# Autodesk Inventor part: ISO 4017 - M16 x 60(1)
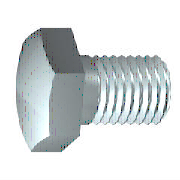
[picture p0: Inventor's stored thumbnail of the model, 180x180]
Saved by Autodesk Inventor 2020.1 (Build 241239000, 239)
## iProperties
Created: 2019-01
Part Number: ISO 4017 - M16 x 60(1)
Material: Stahl, weich
Description: Sechskantschraube
Document SubType Name: Modeling
Standard: DIN EN 24 017
Designer: lutzd
Standards Organization: DIN
Language: de-DE
Size Designation: M16 x 60
Categories: <MemberInstance><Categories><Category DisplayName="Verbindungselemente" InternalName="e4da775c-781d-43d5-af7c-5136215cf5a6" Mnemonic="FSTN"><Category DisplayNam
Mass: 132.821 g
Surface Area: 47.7353 cm^2
Volume: 16.9199 cm^3
Density: 7.85 g/cm^3
Appearance: Halbpoliert
IsCustomPart: 0
Author: lutzd
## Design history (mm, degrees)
workplane "Work Plane1"
sketch "Skizze1"
  geometry: L1 (0, 11.245)-(0, 8); L2 (6, 8)-(60, 8); L3 (60, 8)-(60, 0); L4 (60, 0)-(-0.8, 0); L5 (-12.96, 0)-(72.16, 0) reference; L6 (-0.8, 0)-(-0.8, 11.245); L7 (-0.8, 11.245)-(0, 11.245); L8 (6, 8)-(4.773, 8); L9 (4.773, 8)-(0, 8); L10 (0, -2.249)-(0, 13.494) reference
  constraints: 16 end point, 2 collinear, 2 perpendicular, 1 parallel
  dimensions: "d0" = 60 distance between parallel lines of L3 L1 (= NLG); "d1" = 54 distance from line of L2.start L3 (= GEL); "d2" = 16 diameter of L2 L4 (= GD); "d9" = 0.8001 distance between parallel lines of L6 L1 (computed from SD); "d10" = 22.49 diameter of L7 L4 (= SD2); "d13" = 1.227 distance of L2.start L8.end (computed from GAL); "d14" = 16 diameter of L9 L4 (= BDM)
revolve "Körper" sketch "Skizze1" stored, may be unused: angle "d12" = 90 deg
sketch "Skizze2"
  geometry: L1 (0, 13.856)-(12, 6.928); L2 (12, 6.928)-(12, -6.928); L3 (12, -6.928)-(0, -13.856); L4 (0, -13.856)-(-12, -6.928); L5 (-12, -6.928)-(-12, 6.928); L6 (-12, 6.928)-(0, 13.856); 2 further points
  constraints: 12 end point, 1 coincident, 1 vertical, 11 other
  dimensions: "d11" = 24 distance between parallel lines of L5 L2 (= SW)
extrude "Kopf" join sketch "Skizze2" distance "d3" = 9.2 (= KOH - SD); taper "d4" = 0 deg
sketch "Skizze4"
  geometry: L1 (-10, 12)-(-10, 13.856); L2 (-10, 13.856)-(-8.928, 13.856); L3 (-8.928, 13.856)-(-10, 12); L4 (-11.84, 0)-(1.04, 0) reference; L5 (-0.8, 13.856)-(-10, 13.856) reference; L6 (-10, 6.928)-(-10, 13.856) reference
  constraints: 6 end point, 2 collinear, 1 perpendicular, 1 vertical
  dimensions: "d5" = 30 deg angle of L3 L1 (= ANG1); "d19" = 24 diameter of L1.start L4 (= SW0)
revolve "Fase1" stored, may be unused: angle "d21" = 90 deg
body "Solid1"
feature "Gewinde" dims "d15" = 54 (= GEL), "d16" = 0
chamfer "Fase2" distance "d6" = 1.2269 (= -0.5 x SPD + 0.5 x GD); stored, may be unused: second distance "d7" = 1.227 (computed from GUL), angle "d55" = 45 deg
other parameters: "NLG" = 60 [user parameter; used in 1 equation term], "GD" = 16 (= NND) [user parameter; used in 2 equation terms], "BDM" = 16 (= NND) [user parameter; used in 1 equation term], "KOH" = 10 [user parameter; used in 1 equation term], "GEL" = 54 [user parameter; used in 2 equation terms], "SW" = 24 [user parameter; used in 2 equation terms], "SW0" = 24 (= SW) [user parameter; used in 1 equation term], "SPD" = 13.5462 (= NND - 1.2269 x PTC) [user parameter; used in 1 equation term], "SD2" = 22.49 [user parameter; used in 2 equation terms], "SD" = 0.8 [user parameter; used in 2 equation terms], "ANG1" = 30 deg [user parameter; used in 1 equation term], "GAL" = 1.2269 (= 0.61345 x PTC) [user parameter; used in 1 equation term], "GUL" = 1.2269 (= 0.61345 x PTC) [user parameter; used in 1 equation term], "d8" = 0, "RR" = 0.6 [user parameter], "d57" = 0, "d58" = 0, "TPU" = 5 (computed from PTC) [user parameter], "GD1" = 13.5462 (= THREADDIA - 1.2269 x PTC) [user parameter], "THREADDIA" = 16 [user parameter; used in 1 equation term], "SDH" = 22.49 (= SD2) [user parameter], "SDHG" = 6 [user parameter], "TOA" = 30 deg [user parameter], "PTC" = 2 [user parameter; used in 5 equation terms], "NND" = 16 [user parameter; used in 3 equation terms], "E0" = 27.72 [user parameter]
